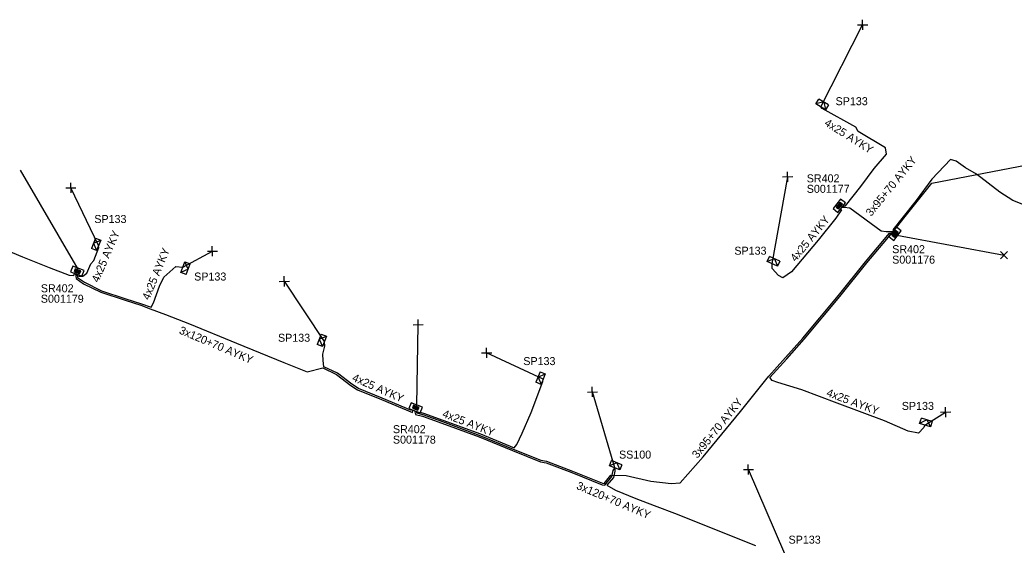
# Model space of a CAD drawing. Extents: x -762504 to -761250, y -1152974 to -1152253.
# Drawn here: x -761655.3 to -761531.9, y -1152323.8 to -1152258.5 of the extents above; entities that cross this region are included whole.
import ezdxf

# ---------------------------------------------------------------- set-up
doc = ezdxf.new("R2010")
doc.units = 0
for name, color, linetype in [('Vrstva 28', 7, 'Continuous'), ('Vrstva 29', 7, 'Continuous'), ('Vrstva 30', 7, 'Continuous'), ('Vrstva 31', 7, 'Continuous'), ('Vrstva 33', 7, 'Continuous'), ('Vrstva 34', 7, 'Continuous'), ('Vrstva 5', 7, 'Continuous'), ('Vrstva 59', 7, 'Continuous'), ('Vrstva 6', 7, 'Continuous')]:
    doc.layers.add(name, color=color, linetype=linetype)

msp = doc.modelspace()

# ---------------------------------------------------------------- linework, layer by layer
at = {"layer": 'Vrstva 28'}
for points in [[(-761553.428, -1152280.781), (-761554.351, -1152281.963)], [(-761553.508, -1152281.191), (-761553.966, -1152281.777)], [(-761553.5, -1152281.257), (-761553.9, -1152281.769)], [(-761553.492, -1152281.323), (-761553.833, -1152281.761)], [(-761553.483, -1152281.39), (-761553.767, -1152281.753)], [(-761553.76, -1152282.425), (-761552.837, -1152281.243)], [(-761553.472, -1152281.451), (-761553.704, -1152281.749)], [(-761553.693, -1152281.811), (-761553.409, -1152281.448)], [(-761553.685, -1152281.877), (-761553.343, -1152281.44)], [(-761553.676, -1152281.943), (-761553.276, -1152281.431)], [(-761553.668, -1152282.01), (-761553.21, -1152281.423)], [(-761553.21, -1152281.423), (-761553.508, -1152281.191)], [(-761553.276, -1152281.431), (-761553.5, -1152281.257)], [(-761553.343, -1152281.44), (-761553.492, -1152281.323)], [(-761553.409, -1152281.448), (-761553.483, -1152281.39)], [(-761552.837, -1152281.243), (-761553.428, -1152280.781)], [(-761554.351, -1152281.963), (-761553.76, -1152282.425)], [(-761553.966, -1152281.777), (-761553.668, -1152282.01)], [(-761553.9, -1152281.769), (-761553.676, -1152281.943)], [(-761553.833, -1152281.761), (-761553.685, -1152281.877)], [(-761553.767, -1152281.753), (-761553.693, -1152281.811)], [(-761546.5, -1152284.265), (-761547.423, -1152285.447)], [(-761546.592, -1152284.68), (-761547.05, -1152285.267)], [(-761547.05, -1152285.267), (-761546.752, -1152285.499)], [(-761546.584, -1152284.747), (-761546.984, -1152285.259)], [(-761546.984, -1152285.259), (-761546.76, -1152285.433)], [(-761546.575, -1152284.813), (-761546.917, -1152285.25)], [(-761546.917, -1152285.25), (-761546.768, -1152285.367)], [(-761546.567, -1152284.879), (-761546.851, -1152285.242)], [(-761546.851, -1152285.242), (-761546.776, -1152285.3)], [(-761546.832, -1152285.909), (-761545.909, -1152284.727)], [(-761546.788, -1152285.239), (-761546.556, -1152284.941)], [(-761546.776, -1152285.3), (-761546.493, -1152284.937)], [(-761546.768, -1152285.367), (-761546.427, -1152284.929)], [(-761546.76, -1152285.433), (-761546.36, -1152284.921)], [(-761546.752, -1152285.499), (-761546.294, -1152284.913)], [(-761546.294, -1152284.913), (-761546.592, -1152284.68)], [(-761546.36, -1152284.921), (-761546.584, -1152284.747)], [(-761546.427, -1152284.929), (-761546.575, -1152284.813)], [(-761546.493, -1152284.937), (-761546.567, -1152284.879)], [(-761545.909, -1152284.727), (-761546.5, -1152284.265)], [(-761547.423, -1152285.447), (-761546.832, -1152285.909)], [(-761648.775, -1152289.134), (-761649.043, -1152289.834)], [(-761649.043, -1152289.834), (-761647.643, -1152290.371)], [(-761647.374, -1152289.671), (-761648.775, -1152289.134)], [(-761648.484, -1152289.448), (-761648.619, -1152289.8)], [(-761648.619, -1152289.8), (-761647.925, -1152290.067)], [(-761648.457, -1152289.509), (-761648.558, -1152289.773)], [(-761648.558, -1152289.773), (-761647.952, -1152290.006)], [(-761648.43, -1152289.57), (-761648.497, -1152289.746)], [(-761648.497, -1152289.746), (-761647.979, -1152289.945)], [(-761647.789, -1152289.714), (-761648.484, -1152289.448)], [(-761647.85, -1152289.741), (-761648.457, -1152289.509)], [(-761648.402, -1152289.631), (-761648.436, -1152289.719)], [(-761648.436, -1152289.719), (-761648.006, -1152289.884)], [(-761647.911, -1152289.769), (-761648.43, -1152289.57)], [(-761647.972, -1152289.796), (-761648.402, -1152289.631)], [(-761648.028, -1152289.825), (-761648.381, -1152289.69)], [(-761648.006, -1152289.884), (-761647.972, -1152289.796)], [(-761647.979, -1152289.945), (-761647.911, -1152289.769)], [(-761647.952, -1152290.006), (-761647.85, -1152289.741)], [(-761647.925, -1152290.067), (-761647.789, -1152289.714)], [(-761647.643, -1152290.371), (-761647.374, -1152289.671)], [(-761606.755, -1152306.094), (-761607.023, -1152306.794)], [(-761605.354, -1152306.631), (-761606.755, -1152306.094)], [(-761607.023, -1152306.794), (-761605.623, -1152307.331)], [(-761606.464, -1152306.408), (-761606.599, -1152306.76)], [(-761606.599, -1152306.76), (-761605.905, -1152307.027)], [(-761606.437, -1152306.469), (-761606.538, -1152306.733)], [(-761606.538, -1152306.733), (-761605.932, -1152306.966)], [(-761606.41, -1152306.53), (-761606.477, -1152306.706)], [(-761606.477, -1152306.706), (-761605.959, -1152306.905)], [(-761605.769, -1152306.674), (-761606.464, -1152306.408)], [(-761605.83, -1152306.701), (-761606.437, -1152306.469)], [(-761606.382, -1152306.591), (-761606.416, -1152306.679)], [(-761606.416, -1152306.679), (-761605.986, -1152306.844)], [(-761605.891, -1152306.729), (-761606.41, -1152306.53)], [(-761605.952, -1152306.756), (-761606.382, -1152306.591)], [(-761606.008, -1152306.785), (-761606.361, -1152306.65)], [(-761605.986, -1152306.844), (-761605.952, -1152306.756)], [(-761605.959, -1152306.905), (-761605.891, -1152306.729)], [(-761605.932, -1152306.966), (-761605.83, -1152306.701)], [(-761605.905, -1152307.027), (-761605.769, -1152306.674)], [(-761605.623, -1152307.331), (-761605.354, -1152306.631)]]:
    msp.add_lwpolyline(points, dxfattribs=at)
at = {"layer": 'Vrstva 31'}
for points in [[(-761554.927, -1152269.072), (-761555.287, -1152269.672), (-761556.487, -1152268.951), (-761556.127, -1152268.351)], [(-761555.527, -1152268.711), (-761556.487, -1152268.951)], [(-761554.927, -1152269.072), (-761556.127, -1152268.351)], [(-761555.527, -1152268.711), (-761555.287, -1152269.672)], [(-761645.962, -1152285.623), (-761646.464, -1152286.93)], [(-761645.962, -1152285.623), (-761645.308, -1152285.874), (-761645.81, -1152287.181), (-761646.464, -1152286.93)], [(-761646.213, -1152286.276), (-761645.308, -1152285.874)], [(-761646.213, -1152286.276), (-761645.81, -1152287.181)], [(-761634.698, -1152290.147), (-761635.352, -1152289.896), (-761634.85, -1152288.589), (-761634.196, -1152288.84)], [(-761634.447, -1152289.494), (-761634.85, -1152288.589)], [(-761634.698, -1152290.147), (-761634.196, -1152288.84)], [(-761560.987, -1152288.492), (-761561.283, -1152289.127), (-761562.552, -1152288.535), (-761562.256, -1152287.901)], [(-761561.621, -1152288.196), (-761562.552, -1152288.535)], [(-761560.987, -1152288.492), (-761562.256, -1152287.901)], [(-761561.621, -1152288.196), (-761561.283, -1152289.127)], [(-761634.447, -1152289.494), (-761635.352, -1152289.896)], [(-761617.912, -1152297.553), (-761618.414, -1152298.86)], [(-761617.912, -1152297.553), (-761617.258, -1152297.804), (-761617.76, -1152299.111), (-761618.414, -1152298.86)], [(-761618.163, -1152298.206), (-761617.258, -1152297.804)], [(-761618.163, -1152298.206), (-761617.76, -1152299.111)], [(-761590.752, -1152302.243), (-761591.254, -1152303.55)], [(-761590.752, -1152302.243), (-761590.098, -1152302.494), (-761590.6, -1152303.801), (-761591.254, -1152303.55)], [(-761591.003, -1152302.896), (-761590.098, -1152302.494)], [(-761591.003, -1152302.896), (-761590.6, -1152303.801)], [(-761542.065, -1152308.421), (-761542.281, -1152309.087), (-761543.613, -1152308.654), (-761543.397, -1152307.988)], [(-761542.731, -1152308.205), (-761543.613, -1152308.654)], [(-761542.065, -1152308.421), (-761543.397, -1152307.988)], [(-761542.731, -1152308.205), (-761542.281, -1152309.087)], [(-761580.573, -1152313.788), (-761580.824, -1152314.442), (-761582.131, -1152313.94), (-761581.88, -1152313.286)], [(-761581.226, -1152313.537), (-761582.131, -1152313.94)], [(-761580.573, -1152313.788), (-761581.88, -1152313.286)], [(-761581.226, -1152313.537), (-761580.824, -1152314.442)]]:
    msp.add_lwpolyline(points, dxfattribs=at)
at = {"layer": 'Vrstva 34'}
for points in [[(-761551.315, -1152259.141), (-761550.065, -1152259.119)], [(-761550.679, -1152259.755), (-761550.701, -1152258.505)], [(-761559.989, -1152278.625), (-761560.011, -1152277.375)], [(-761648.989, -1152280.005), (-761649.011, -1152278.755)], [(-761560.625, -1152278.011), (-761559.375, -1152277.989)], [(-761649.625, -1152279.391), (-761648.375, -1152279.369)], [(-761632.065, -1152287.261), (-761630.815, -1152287.239)], [(-761631.429, -1152287.875), (-761631.451, -1152286.625)], [(-761533.572, -1152287.308), (-761532.688, -1152288.192)], [(-761533.572, -1152288.192), (-761532.688, -1152287.308)], [(-761623.125, -1152291.011), (-761621.875, -1152290.989)], [(-761622.489, -1152291.625), (-761622.511, -1152290.375)], [(-761606.505, -1152296.391), (-761605.255, -1152296.369)], [(-761605.869, -1152297.005), (-761605.891, -1152295.755)], [(-761598.005, -1152299.891), (-761596.755, -1152299.869)], [(-761597.369, -1152300.505), (-761597.391, -1152299.255)], [(-761584.875, -1152304.761), (-761583.625, -1152304.739)], [(-761584.239, -1152305.375), (-761584.261, -1152304.125)], [(-761541.005, -1152307.261), (-761539.755, -1152307.239)], [(-761540.369, -1152307.875), (-761540.391, -1152306.625)], [(-761565.505, -1152314.391), (-761564.255, -1152314.369)], [(-761564.869, -1152315.005), (-761564.891, -1152313.755)]]:
    msp.add_lwpolyline(points, dxfattribs=at)
at = {"layer": 'Vrstva 5'}
for points in [[(-761648.6, -1152289.99), (-761648.69, -1152290.32), (-761649.19, -1152290.28), (-761651.67, -1152289.32), (-761654.97, -1152288.01), (-761661.13, -1152285.42), (-761663.93, -1152284.42), (-761667.23, -1152283.04), (-761670.12, -1152281.75), (-761674.31, -1152280.06), (-761679.7, -1152277.9), (-761684.72, -1152276.28), (-761689.26, -1152274.88), (-761691.3, -1152274.22), (-761696.12, -1152272.01), (-761698.99, -1152270.39), (-761699.89, -1152269.51), (-761699.98, -1152268.24), (-761700.03, -1152267.76)], [(-761553.14, -1152281.63), (-761552.82, -1152281.63), (-761550.92, -1152279.2), (-761549.25, -1152276.99), (-761547.73, -1152275.19), (-761547.84, -1152274.42), (-761551.23, -1152272.37), (-761551.54, -1152271.84), (-761555.73, -1152269.52), (-761555.89, -1152269.31)], [(-761518.86, -1152288.77), (-761522.69, -1152286.1), (-761523.66, -1152285.17), (-761524.24, -1152284.3), (-761527.44, -1152282.79), (-761532.03, -1152280.96), (-761533.66, -1152279.92), (-761536.57, -1152277.67), (-761537.9, -1152276.88), (-761539.08, -1152276.05), (-761539.78, -1152275.86), (-761542.08, -1152278.31), (-761544.06, -1152280.96), (-761545.65, -1152282.98), (-761546.96, -1152284.58), (-761546.86, -1152284.73)], [(-761553.42, -1152281.99), (-761553.31, -1152282.12), (-761554.03, -1152283.17), (-761556.22, -1152285.87), (-761559.52, -1152289.83), (-761560.58, -1152290.57), (-761561.15, -1152290.27), (-761561.92, -1152289.39), (-761561.92, -1152288.83)], [(-761546.96, -1152284.86), (-761547.77, -1152284.83), (-761548.4, -1152284.77), (-761552.3, -1152281.9), (-761552.98, -1152281.83), (-761553.3, -1152281.83)], [(-761546.5, -1152284.33), (-761545.39, -1152282.93)], [(-761606.14, -1152307.14), (-761606.11, -1152307.36), (-761605.29, -1152307.57), (-761602.88, -1152308.43), (-761598.23, -1152310.15), (-761594.1, -1152311.85), (-761590.64, -1152313.23), (-761589.93, -1152313.37), (-761586.74, -1152314.59), (-761582.99, -1152316.1), (-761582.79, -1152316.13), (-761581.94, -1152315.1), (-761580.04, -1152315.12), (-761576.98, -1152315.82), (-761574.46, -1152316.11), (-761573.36, -1152316.06), (-761570.5, -1152312.82), (-761565.86, -1152307.17), (-761562.7, -1152303.25), (-761562.35, -1152302.79), (-761560.26, -1152300.48), (-761558.12, -1152298.05), (-761553.69, -1152292.78), (-761550.34, -1152288.57), (-761547.36, -1152285), (-761547.08, -1152285.01)], [(-761542.95, -1152308.87), (-761543.08, -1152309.15), (-761543.76, -1152309.85), (-761545.04, -1152309.63), (-761547.99, -1152308.33), (-761553.86, -1152306.14), (-761558.23, -1152304.5), (-761561.21, -1152303.57), (-761561.94, -1152303.31), (-761562.22, -1152302.94), (-761560.11, -1152300.62), (-761557.96, -1152298.18), (-761553.53, -1152292.9), (-761550.18, -1152288.69), (-761547.7, -1152285.75), (-761547.25, -1152285.2)], [(-761648.05, -1152290.21), (-761648.03, -1152290.36), (-761647.51, -1152290.35), (-761647.03, -1152289.98), (-761646.55, -1152288.83), (-761646.17, -1152288.41), (-761645.54, -1152286.78), (-761645.56, -1152286.53)], [(-761648.45, -1152290.06), (-761648.37, -1152290.65), (-761647.43, -1152291.3), (-761645.27, -1152292.36), (-761642.26, -1152293.35), (-761640.31, -1152293.96), (-761639.15, -1152294.41), (-761637.27, -1152295.11), (-761634.3, -1152296.29), (-761628.44, -1152298.7), (-761622.58, -1152301.07), (-761619.67, -1152302.24), (-761617.74, -1152301.76), (-761616.01, -1152302.58), (-761614.23, -1152303.96), (-761613.4, -1152304.49), (-761610.42, -1152305.69), (-761606.6, -1152307.32), (-761606.51, -1152306.98)], [(-761648.23, -1152290.14), (-761648.19, -1152290.53), (-761647.33, -1152291.12), (-761645.19, -1152292.18), (-761642.2, -1152293.16), (-761640.25, -1152293.78), (-761639.06, -1152294.23), (-761638.74, -1152293.67), (-761638.01, -1152291.62), (-761637.46, -1152290.5), (-761635.96, -1152289.15), (-761635.1, -1152289.24)], [(-761606.69, -1152306.91), (-761606.73, -1152307.05), (-761610.34, -1152305.51), (-761613.3, -1152304.31), (-761614.11, -1152303.8), (-761615.91, -1152302.4), (-761617.58, -1152301.61), (-761617.68, -1152300.82), (-761617.71, -1152300.04), (-761617.46, -1152299.04), (-761617.51, -1152298.46)], [(-761605.68, -1152307.26), (-761605.23, -1152307.38), (-761602.81, -1152308.24), (-761598.16, -1152309.96), (-761593.97, -1152311.69), (-761593.62, -1152311.27), (-761592.95, -1152309.85), (-761591.87, -1152307.29), (-761590.39, -1152303.43), (-761590.35, -1152303.15)], [(-761606.32, -1152307.06), (-761606.23, -1152307.53), (-761605.35, -1152307.76), (-761602.95, -1152308.62), (-761598.3, -1152310.34), (-761594.18, -1152312.03), (-761590.7, -1152313.43), (-761589.99, -1152313.57), (-761586.82, -1152314.77), (-761583.05, -1152316.3), (-761582.71, -1152316.34), (-761581.82, -1152315.27), (-761581.66, -1152314.53), (-761581.48, -1152314.19), (-761581.46, -1152314.58), (-761581.63, -1152315.36), (-761582.45, -1152316.35), (-761581.38, -1152316.96), (-761578.87, -1152318.01), (-761576.56, -1152318.88), (-761573.74, -1152319.93), (-761568.45, -1152322.04), (-761563.99, -1152323.83)]]:
    msp.add_lwpolyline(points, dxfattribs=at)
at = {"layer": 'Vrstva 59'}
for points in [[(-761555.89, -1152269.31), (-761550.69, -1152259.13)], [(-761545.39, -1152282.93), (-761542.09, -1152278.79), (-761517.34, -1152274.04)], [(-761648.1, -1152289.47), (-761655.25, -1152277.19)], [(-761561.92, -1152288.83), (-761560, -1152278)], [(-761645.56, -1152286.53), (-761649, -1152279.38)], [(-761546.44, -1152285.26), (-761533.13, -1152287.75)], [(-761635.1, -1152289.24), (-761631.44, -1152287.25)], [(-761617.51, -1152298.46), (-761622.5, -1152291)], [(-761606.07, -1152306.42), (-761605.88, -1152296.38)], [(-761590.35, -1152303.15), (-761597.38, -1152299.88)], [(-761581.48, -1152314.19), (-761584.25, -1152304.75)], [(-761542.95, -1152308.87), (-761540.38, -1152307.25)], [(-761560.37, -1152324.86), (-761564.88, -1152314.38)]]:
    msp.add_lwpolyline(points, dxfattribs=at)

# ---------------------------------------------------------------- texts
at = {"layer": 'Vrstva 29'}
for s, p in [('S001177', (-761557.63, -1152280)), ('S001176', (-761547.02, -1152288.8)), ('S001179', (-761652.74, -1152293.66)), ('S001178', (-761609.02, -1152311.17))]:
    msp.add_text(s, height=0.9943, dxfattribs=at).set_placement(p)
at = {"layer": 'Vrstva 30'}
for p in [(-761557.63, -1152278.7), (-761547.02, -1152287.5), (-761652.74, -1152292.36), (-761609.02, -1152309.87)]:
    msp.add_text('SR402', height=0.9943, dxfattribs=at).set_placement(p)
at = {"layer": 'Vrstva 33'}
for s, p in [('SP133', (-761554.05, -1152269.11)), ('SP133', (-761646.1, -1152283.75)), ('SP133', (-761566.62, -1152287.69)), ('SP133', (-761633.7, -1152290.9)), ('SP133', (-761623.29, -1152298.51)), ('SP133', (-761592.83, -1152301.41)), ('SP133', (-761545.83, -1152306.98)), ('SS100', (-761580.94, -1152313.03)), ('SP133', (-761559.89, -1152323.6))]:
    msp.add_text(s, height=0.9943, dxfattribs=at).set_placement(p)
at = {"layer": 'Vrstva 6'}
for s, height, rotation, p in [('4x25 AYKY', 0.9943, 327.85549, (-761555.53, -1152271.56)), ('3x95+70 AYKY', 0.99429, 50.84254, (-761549.63, -1152283)), ('4x25 AYKY', 0.9943, 50.86889, (-761559, -1152288.64)), ('4x25 AYKY', 0.9943, 66.81338, (-761645.58, -1152291.21)), ('4x25 AYKY', 0.9943, 67.62689, (-761639.29, -1152293.4)), ('3x120+70 AYKY', 0.99429, 337.01117, (-761635.66, -1152297.45)), ('4x25 AYKY', 0.9943, 336.19406, (-761614.17, -1152303.33)), ('4x25 AYKY', 0.9943, 339.32956, (-761555.26, -1152305.22)), ('3x95+70 AYKY', 0.99429, 51.08853, (-761571.21, -1152313.08)), ('4x25 AYKY', 0.9943, 338.79911, (-761602.96, -1152307.83)), ('3x120+70 AYKY', 0.99429, 337.11738, (-761586.32, -1152316.76))]:
    msp.add_text(s, height=height, rotation=rotation, dxfattribs=at).set_placement(p)

doc.saveas('drawing.dxf')
